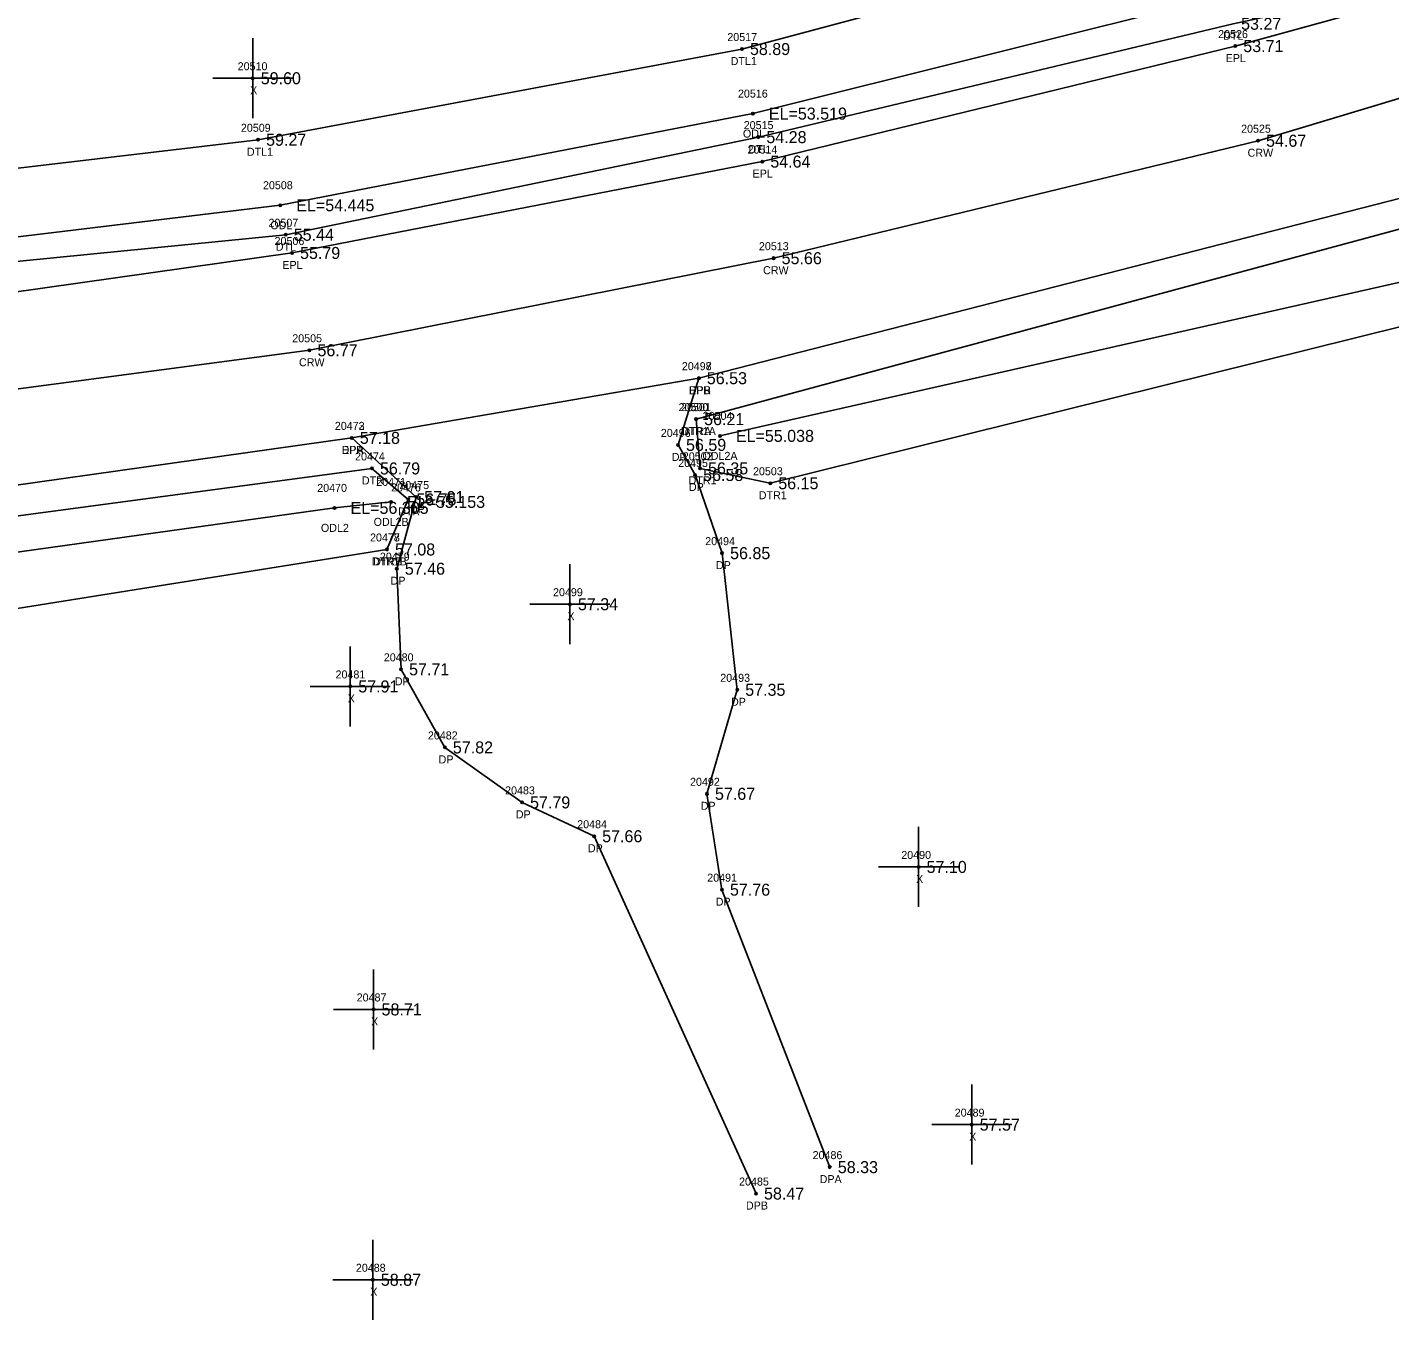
# Model space of a CAD drawing. Extents: x 2420351 to 2422725, y 845330 to 846558.
# Drawn here: x 2421379.3 to 2421549.5, y 845570.9 to 845732.5 of the extents above; entities that cross this region are included whole.
import ezdxf

# ---------------------------------------------------------------- set-up
doc = ezdxf.new("R2010")
doc.units = 0
for name, color, linetype in [('RD_DTM_BkLn1', 7, 'Continuous'), ('RD_EX_Driveway', 7, 'Continuous'), ('RD_EX_Driveway_txCode', 7, 'Continuous'), ('RD_EX_H2O', 7, 'Continuous'), ('RD_EX_H2O_txCode', 7, 'Continuous'), ('RD_EX_Misc', 7, 'Continuous'), ('RD_EX_Misc_txCode', 7, 'Continuous'), ('RD_EX_Road', 7, 'Continuous'), ('RD_EX_Road_txCode', 7, 'Continuous'), ('RD_EX_TX_Driveway_ELEV', 7, 'Continuous'), ('RD_EX_TX_H2O_ELEV', 7, 'Continuous'), ('RD_EX_TX_Misc_ELEV', 7, 'Continuous'), ('RD_EX_TX_Road_ELEV', 7, 'Continuous'), ('RD_HC_Survey_ELEV', 7, 'Continuous'), ('RD_HC_Survey_txCode', 7, 'Continuous'), ('RD_SMD_Locator', 7, 'Continuous')]:
    doc.layers.add(name, color=color, linetype=linetype)

msp = doc.modelspace()

# ---------------------------------------------------------------- linework, layer by layer
at = {"layer": 'RD_DTM_BkLn1'}
msp.add_lwpolyline([(2420378.71, 845690.53), (2420439.5, 845704.09), (2420489.95, 845712.49), (2420551.89, 845719.42), (2420551.95, 845719.57), (2420607.12, 845722.67), (2420682.92, 845723.04), (2420749.65, 845719.68), (2420796.31, 845715.7), (2420900.74, 845705.33), (2421018.16, 845694.11), (2421114.61, 845684.8), (2421175.74, 845680.1), (2421234.97, 845678.35), (2421292.42, 845679.46), (2421350.56, 845683.65), (2421414.53, 845692.12), (2421472.54, 845703.63), (2421533.08, 845718.31), (2421555.4, 845725.02), (2421609.81, 845741.71), (2421666.58, 845762.88), (2421744.67, 845798.22)], dxfattribs=at)
at = {"layer": 'RD_EX_Driveway'}
for points in [[(2421479.56, 845590.02), (2421466.08, 845624.7), (2421464.21, 845636.68), (2421467.99, 845649.68), (2421466.1, 845666.76), (2421462.73, 845676.53), (2421460.59, 845680.29), (2421463.19, 845688.63)], [(2421419.82, 845681.17), (2421427.87, 845673.77), (2421425.45, 845664.82), (2421425.98, 845652.24), (2421431.45, 845642.48), (2421441.1, 845635.61), (2421450.11, 845631.38), (2421470.34, 845586.72)]]:
    msp.add_lwpolyline(points, dxfattribs=at)
at = {"layer": 'RD_EX_H2O'}
for points in [[(2420975.55, 846190.58), (2420976.37, 846105.11), (2420974.31, 845997.82), (2420976.03, 845896.74), (2420974.59, 845794.18), (2420975.37, 845743.63), (2420984.12, 845720.99), (2420999.91, 845711.18), (2421116.7, 845699.77), (2421177.35, 845696.01), (2421236.57, 845694.11), (2421292.07, 845694.75), (2421349.67, 845700.43), (2421411.57, 845706.56), (2421470.63, 845718.76), (2421529.96, 845732.93), (2421551.14, 845737.51), (2421602.97, 845753.33), (2421656.85, 845776.48), (2421724.45, 845805.15), (2421739.21, 845812.56)], [(2420980.17, 846190.47), (2420980.93, 846104.85), (2420980.02, 845997.99), (2420979.17, 845896.92), (2420978.72, 845794), (2420978.72, 845743.89), (2420987.58, 845724.3), (2421000.53, 845717.13), (2421117.24, 845704.33), (2421178.3, 845699.94), (2421237.1, 845697.97), (2421292.37, 845698.66), (2421349.43, 845702.84), (2421410.88, 845710.25), (2421469.94, 845721.7), (2421529.19, 845736.54), (2421550.26, 845742.27), (2421602, 845757.38), (2421655.89, 845778.44), (2421721.41, 845810.89), (2421742.22, 845823.45)], [(2421348.44, 845711.4), (2421408.11, 845718.43), (2421468.58, 845729.77), (2421526.52, 845745.24), (2421541.81, 845745.64), (2421549.75, 845745.7), (2421570.45, 845751.87), (2421591.88, 845757.66), (2421599.3, 845765.73), (2421650.04, 845787.07), (2421668.02, 845786.79), (2421719.15, 845813.59), (2421740.13, 845828.42)], [(2421462.85, 845683.51), (2421560.11, 845709.79), (2421615.97, 845726.65), (2421668.49, 845745.18), (2421738.54, 845774.52), (2421754.61, 845783.24)], [(2421462.85, 845683.51), (2421463.34, 845677.36), (2421472.12, 845675.5), (2421563.69, 845698.26), (2421619.71, 845715.72), (2421671.24, 845734.85), (2421744.95, 845763.45), (2421768.08, 845778.29)], [(2421465.82, 845681.42), (2421562.1, 845703.19), (2421618.04, 845721.04), (2421670.65, 845738.09), (2421741.88, 845769.36), (2421759.06, 845777.16)], [(2420681.02, 845707.72), (2420749.24, 845704.74), (2420794.5, 845700.07), (2420899.98, 845690.96), (2421017.54, 845678.31), (2421112.89, 845668.07), (2421174.6, 845666.39), (2421234.64, 845664.08), (2421293.38, 845665.28), (2421351.67, 845667.88), (2421422.34, 845677.35), (2421426.88, 845673.47), (2421424.22, 845667.22)], [(2420680.88, 845704.69), (2420749.16, 845701.08), (2420794.33, 845696.81), (2420899.79, 845687.85), (2421017.53, 845674.81), (2421112.48, 845665.13), (2421174.04, 845661.58), (2421234.82, 845660.24), (2421294.09, 845659.38), (2421352.01, 845663.24), (2421417.66, 845672.42), (2421424.72, 845673.17)], [(2420681.1, 845702.44), (2420748.92, 845698.41), (2420794.23, 845693.69), (2420899.45, 845684.25), (2421017.43, 845671.31), (2421111.87, 845660.39), (2421174.2, 845656.63), (2421235.06, 845654.38), (2421294.9, 845653.67), (2421353.19, 845655.89), (2421424.22, 845667.22)]]:
    msp.add_lwpolyline(points, dxfattribs=at)
at = {"layer": 'RD_EX_Misc'}
for p, q in [((2421407.44, 845721.12), (2421407.44, 845731.12)), ((2421402.44, 845726.12), (2421412.44, 845726.12)), ((2421447.08, 845655.38), (2421447.08, 845665.38)), ((2421442.08, 845660.38), (2421452.08, 845660.38)), ((2421419.63, 845645.1), (2421419.63, 845655.1)), ((2421414.63, 845650.1), (2421424.63, 845650.1)), ((2421490.65, 845622.54), (2421490.65, 845632.54)), ((2421485.65, 845627.54), (2421495.65, 845627.54)), ((2421422.54, 845604.73), (2421422.54, 845614.73)), ((2421417.54, 845609.73), (2421427.54, 845609.73)), ((2421497.29, 845590.33), (2421497.29, 845600.33)), ((2421492.29, 845595.33), (2421502.29, 845595.33)), ((2421422.45, 845570.94), (2421422.45, 845580.94)), ((2421417.45, 845575.94), (2421427.45, 845575.94))]:
    msp.add_line(p, q, dxfattribs=at)
at = {"layer": 'RD_EX_Road'}
for points in [[(2420388.28, 845680.39), (2420441.29, 845692.04), (2420492.62, 845700.7), (2420553.92, 845707.41), (2420607.69, 845710.85), (2420682.38, 845711.26), (2420749.44, 845707.27), (2420795.12, 845703.44), (2420900.28, 845693.42), (2421017.17, 845682.19), (2421113.9, 845672.97), (2421174.87, 845668.16), (2421234.59, 845666.13), (2421293, 845667.25), (2421351.24, 845671.5), (2421419.82, 845681.17), (2421463.19, 845688.63), (2421558.82, 845713.18), (2421614.57, 845730.45), (2421670.73, 845751.42), (2421735.61, 845780.5), (2421750.75, 845787.87), (2421744.67, 845798.22), (2421739.21, 845808.11)], [(2421350.22, 845695.49), (2421412.35, 845704.28), (2421471.12, 845715.7), (2421530.23, 845730.14), (2421551.47, 845736), (2421603.47, 845751.93), (2421659.09, 845772.43), (2421726.04, 845802.13), (2421739.21, 845808.11)]]:
    msp.add_lwpolyline(points, dxfattribs=at)
at = {"layer": 'RD_SMD_Locator'}
for centre in [(2421468.58, 845729.77), (2421530.23, 845730.14), (2421407.44, 845726.12), (2421469.94, 845721.7), (2421470.63, 845718.76), (2421408.11, 845718.43), (2421533.08, 845718.31), (2421471.12, 845715.7), (2421410.88, 845710.25), (2421411.57, 845706.56), (2421412.35, 845704.28), (2421472.54, 845703.63), (2421414.53, 845692.12), (2421463.19, 845688.63), (2421463.19, 845688.63), (2421462.85, 845683.51), (2421462.85, 845683.51), (2421419.82, 845681.17), (2421419.82, 845681.17), (2421465.82, 845681.42), (2421460.59, 845680.29), (2421422.34, 845677.35), (2421462.73, 845676.53), (2421463.34, 845677.36), (2421472.12, 845675.5), (2421424.72, 845673.17), (2421426.88, 845673.47), (2421427.87, 845673.77), (2421417.66, 845672.42), (2421424.22, 845667.22), (2421424.22, 845667.22), (2421466.1, 845666.76), (2421425.45, 845664.82), (2421447.08, 845660.38), (2421425.98, 845652.24), (2421419.63, 845650.1), (2421467.99, 845649.68), (2421431.45, 845642.48), (2421441.1, 845635.61), (2421464.21, 845636.68), (2421450.11, 845631.38), (2421490.65, 845627.54), (2421466.08, 845624.7), (2421422.54, 845609.73), (2421497.29, 845595.33), (2421479.56, 845590.02), (2421470.34, 845586.72), (2421422.45, 845575.94)]:
    msp.add_circle(centre, 0.15, dxfattribs=at)

# ---------------------------------------------------------------- texts
at = {"layer": 'RD_EX_Driveway_txCode'}
for s, p in [('20497', (2421461.07, 845689.63)), ('DPB', (2421461.94, 845686.63)), ('20473', (2421417.7, 845682.17)), ('20496', (2421458.44, 845681.29)), ('DPA', (2421418.55, 845679.17)), ('DP', (2421459.81, 845678.29)), ('20495', (2421460.61, 845677.53)), ('20475', (2421425.76, 845674.77)), ('DP', (2421461.95, 845674.53)), ('DP', (2421427.09, 845671.77)), ('20494', (2421463.99, 845667.76)), ('20479', (2421423.33, 845665.82)), ('DP', (2421465.33, 845664.76)), ('DP', (2421424.67, 845662.82)), ('20480', (2421423.82, 845653.24)), ('DP', (2421425.2, 845650.24)), ('20493', (2421465.87, 845650.68)), ('DP', (2421467.21, 845647.68)), ('20482', (2421429.33, 845643.48)), ('DP', (2421430.67, 845640.48)), ('20492', (2421462.09, 845637.68)), ('20483', (2421438.98, 845636.61)), ('DP', (2421463.43, 845634.68)), ('DP', (2421440.32, 845633.61)), ('20484', (2421447.99, 845632.38)), ('DP', (2421449.33, 845629.38)), ('20491', (2421464.24, 845625.7)), ('DP', (2421465.3, 845622.7)), ('20486', (2421477.41, 845591.02)), ('20485', (2421468.22, 845587.72)), ('DPA', (2421478.29, 845588.02)), ('DPB', (2421469.08, 845584.72))]:
    msp.add_text(s, height=1, dxfattribs=at).set_placement(p)
at = {"layer": 'RD_EX_H2O_txCode'}
for s, p in [('20517', (2421466.75, 845730.77)), ('DTL', (2421528.72, 845730.93)), ('DTL1', (2421467.17, 845727.77)), ('20516', (2421468.08, 845723.7)), ('20509', (2421405.96, 845719.43)), ('20515', (2421468.8, 845719.76)), ('ODL', (2421468.7, 845718.7)), ('DTL1', (2421406.71, 845716.43)), ('DTL', (2421469.39, 845716.76)), ('20508', (2421408.72, 845712.25)), ('20507', (2421409.41, 845707.56)), ('ODL', (2421409.64, 845707.25)), ('DTL', (2421410.32, 845704.56)), ('20500', (2421460.66, 845684.51)), ('20501', (2421460.98, 845684.51)), ('20504', (2421463.67, 845683.42)), ('DTR1A', (2421460.93, 845681.51)), ('DTRA', (2421461.1, 845681.51)), ('20474', (2421420.23, 845678.35)), ('20502', (2421461.19, 845678.36)), ('ODL2A', (2421463.64, 845678.42)), ('DTR', (2421421.08, 845675.35)), ('20471', (2421422.88, 845675.17)), ('DTR1', (2421461.91, 845675.36)), ('20503', (2421469.96, 845676.5)), ('20470', (2421415.5, 845674.42)), ('20476', (2421424.74, 845674.47)), ('DTR1', (2421470.68, 845673.5)), ('ODL2B', (2421422.55, 845670.17)), ('DTR', (2421425.61, 845671.47)), ('ODL2', (2421415.96, 845669.42)), ('20477', (2421422.1, 845668.22)), ('20478', (2421422.1, 845668.22)), ('DTR1B', (2421422.31, 845665.22)), ('DTRB', (2421422.48, 845665.22))]:
    msp.add_text(s, height=1, dxfattribs=at).set_placement(p)
at = {"layer": 'RD_EX_Misc_txCode'}
for s, p in [('20510', (2421405.56, 845727.12)), ('X', (2421407.12, 845724.12)), ('20499', (2421444.97, 845661.38)), ('X', (2421446.77, 845658.38)), ('20481', (2421417.79, 845651.1)), ('X', (2421419.31, 845648.1)), ('20490', (2421488.49, 845628.54)), ('X', (2421490.34, 845625.54)), ('20487', (2421420.43, 845610.73)), ('X', (2421422.23, 845607.73)), ('20489', (2421495.17, 845596.33)), ('X', (2421496.98, 845593.33)), ('20488', (2421420.33, 845576.94)), ('X', (2421422.13, 845573.94))]:
    msp.add_text(s, height=1, dxfattribs=at).set_placement(p)
at = {"layer": 'RD_EX_Road_txCode'}
for s, p in [('20526', (2421528.09, 845731.14)), ('EPL', (2421529.03, 845728.14)), ('20514', (2421469.28, 845716.7)), ('EPL', (2421469.91, 845713.7)), ('20506', (2421410.17, 845705.28)), ('EPL', (2421411.14, 845702.28)), ('20498', (2421461.07, 845689.63)), ('EPR', (2421461.96, 845686.63)), ('20472', (2421417.7, 845682.17)), ('EPR', (2421418.59, 845679.17))]:
    msp.add_text(s, height=1, dxfattribs=at).set_placement(p)
at = {"layer": 'RD_EX_TX_Driveway_ELEV'}
for s, p in [('56.53', (2421464.19, 845687.88)), ('57.18', (2421420.82, 845680.42)), ('56.59', (2421461.59, 845679.54)), ('56.58', (2421463.73, 845675.78)), ('57.01', (2421428.87, 845673.02)), ('56.85', (2421467.1, 845666.01)), ('57.46', (2421426.45, 845664.07)), ('57.71', (2421426.98, 845651.49)), ('57.35', (2421468.99, 845648.93)), ('57.82', (2421432.45, 845641.73)), ('57.67', (2421465.21, 845635.93)), ('57.79', (2421442.1, 845634.86)), ('57.66', (2421451.11, 845630.63)), ('57.76', (2421467.08, 845623.95)), ('58.33', (2421480.56, 845589.27)), ('58.47', (2421471.34, 845585.97))]:
    msp.add_text(s, height=1.5, dxfattribs=at).set_placement(p)
at = {"layer": 'RD_EX_TX_H2O_ELEV'}
for s, p in [('53.27', (2421530.96, 845732.18)), ('58.89', (2421469.58, 845729.02)), ('EL=53.519', (2421471.94, 845720.95)), ('59.27', (2421409.11, 845717.68)), ('54.28', (2421471.63, 845718.01)), ('EL=54.445', (2421412.88, 845709.5)), ('55.44', (2421412.57, 845705.81)), ('56.21', (2421463.85, 845682.76)), ('56.21', (2421463.85, 845682.76)), ('EL=55.038', (2421467.82, 845680.67)), ('56.79', (2421423.34, 845676.6)), ('56.35', (2421464.34, 845676.61)), ('56.15', (2421473.12, 845674.75)), ('EL=56.305', (2421419.66, 845671.67)), ('EL=55.153', (2421426.72, 845672.42)), ('56.75', (2421427.88, 845672.72)), ('57.08', (2421425.22, 845666.47)), ('57.08', (2421425.22, 845666.47))]:
    msp.add_text(s, height=1.5, dxfattribs=at).set_placement(p)
at = {"layer": 'RD_EX_TX_Misc_ELEV'}
for s, p in [('59.60', (2421408.44, 845725.37)), ('57.34', (2421448.08, 845659.63)), ('57.91', (2421420.63, 845649.35)), ('57.10', (2421491.65, 845626.79)), ('58.71', (2421423.54, 845608.98)), ('57.57', (2421498.29, 845594.58)), ('58.87', (2421423.45, 845575.19))]:
    msp.add_text(s, height=1.5, dxfattribs=at).set_placement(p)
at = {"layer": 'RD_EX_TX_Road_ELEV'}
for s, p in [('53.71', (2421531.23, 845729.39)), ('54.64', (2421472.12, 845714.95)), ('55.79', (2421413.35, 845703.53)), ('56.53', (2421464.19, 845687.88)), ('57.18', (2421420.82, 845680.42))]:
    msp.add_text(s, height=1.5, dxfattribs=at).set_placement(p)
at = {"layer": 'RD_HC_Survey_ELEV'}
for s, p in [('54.67', (2421534.08, 845717.56)), ('55.66', (2421473.54, 845702.88)), ('56.77', (2421415.53, 845691.37))]:
    msp.add_text(s, height=1.5, dxfattribs=at).set_placement(p)
at = {"layer": 'RD_HC_Survey_txCode'}
for s, p in [('20525', (2421530.96, 845719.31)), ('CRW', (2421531.77, 845716.31)), ('20513', (2421470.7, 845704.63)), ('CRW', (2421471.22, 845701.63)), ('20505', (2421412.38, 845693.12)), ('CRW', (2421413.22, 845690.12))]:
    msp.add_text(s, height=1, dxfattribs=at).set_placement(p)

doc.saveas('drawing.dxf')
